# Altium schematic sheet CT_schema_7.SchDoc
size 365 x 245 mm
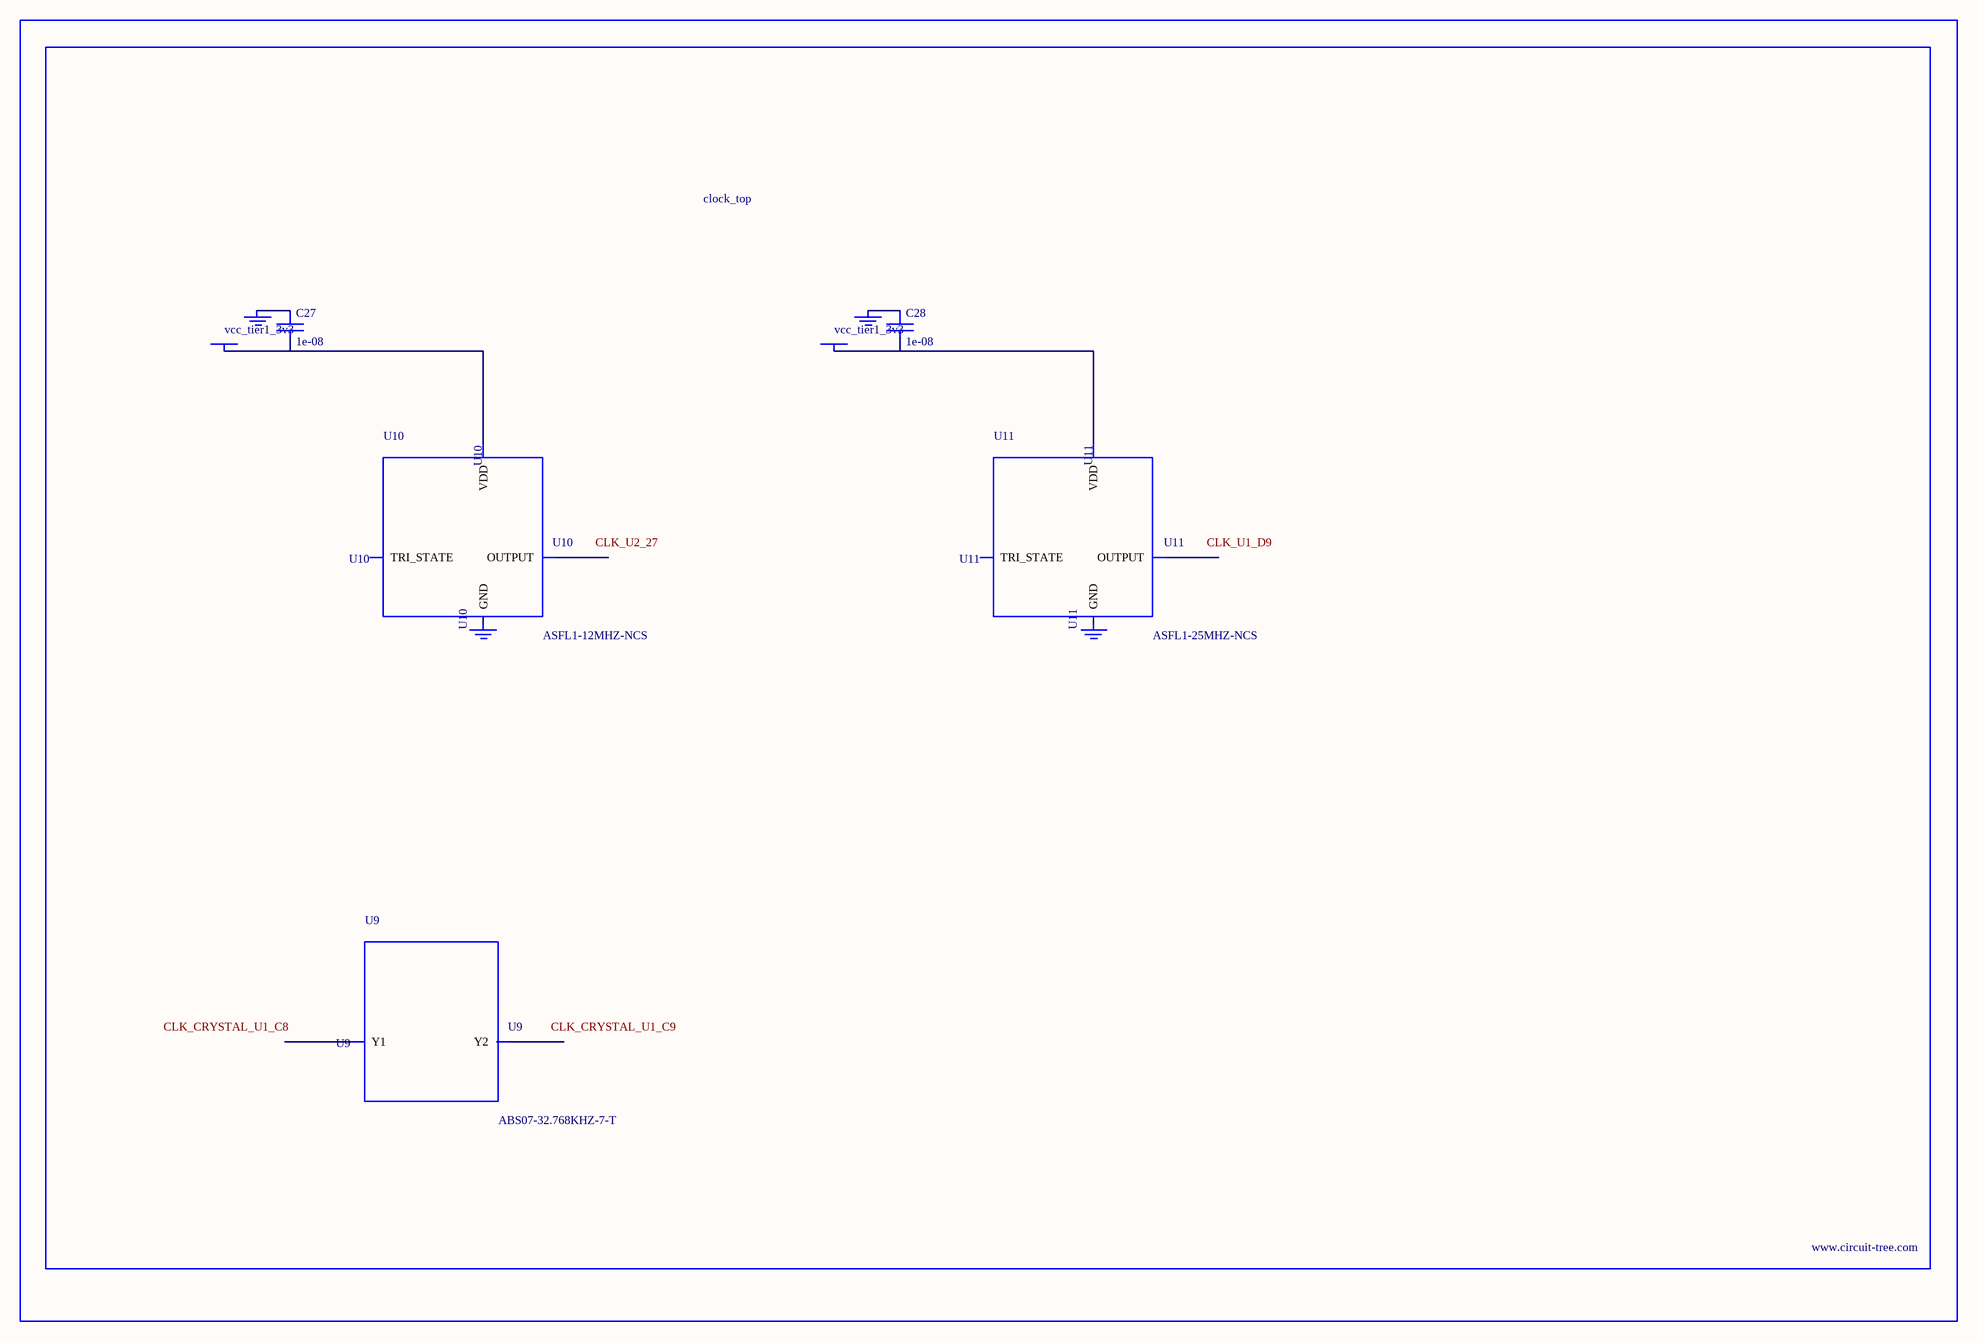
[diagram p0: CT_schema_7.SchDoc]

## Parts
BORDER6  (no value)
C27  1e-08  [C0402]
C28  1e-08  [C0402]
GND_INSTANCE_6_0  (no value)
GND_INSTANCE_6_1  (no value)
GND_INSTANCE_6_2  (no value)
GND_INSTANCE_6_3  (no value)
POWER_INSTANCE_6_0  vcc_tier1_3v3
POWER_INSTANCE_6_1  vcc_tier1_3v3
U9  ABS07-32.768KHZ-7-T  [ABS07-32.768KHZ-7-T]
U10  ASFL1-12MHZ-NCS  [ASFL1]
U11  ASFL1-25MHZ-NCS  [ASFL1]

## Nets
NetC27_1: C27.1 GND_INSTANCE_6_0.0(GND)
NetC27_2: C27.2 POWER_INSTANCE_6_0.0(PWR) U10.4(VDD)
NetC28_1: C28.1 GND_INSTANCE_6_2.0(GND)
NetC28_2: C28.2 POWER_INSTANCE_6_1.0(PWR) U11.4(VDD)

Not connected (* = marked no-connect by the designer): GND_INSTANCE_6_1 0(GND); GND_INSTANCE_6_3 0(GND); U9 1(Y1) 2(Y2); U10 1(TRI_STATE) 2(GND) 3(OUTPUT); U11 1(TRI_STATE) 2(GND) 3(OUTPUT)

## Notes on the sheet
- Labels drawn without touching a wire or pin: CLK_CRYSTAL_U1_C8, CLK_CRYSTAL_U1_C9, CLK_U1_D9, CLK_U2_27

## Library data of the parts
BORDER6 = BORDER_PAGE6
C27 C28 = C0402C103K3RAC
GND_INSTANCE_6_0-GND_INSTANCE_6_3 = GND
POWER_INSTANCE_6_0 POWER_INSTANCE_6_1 = PWR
